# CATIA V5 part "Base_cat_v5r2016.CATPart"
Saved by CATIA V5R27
Part number: Base
Nomenclature: 1
Bounding box of the stored display mesh (mm): x -32 to 32, y 0 to 144, z 0 to 52
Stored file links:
  E:\_Deepak\2017_Deepak\CATIA\Resources\Tutorial Files\Tutorials\c13_catia_v5_6r2016_tut\c13tut2\c13tut02.CATParts\Base_cat_v5r2016.CATPart
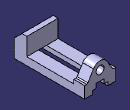
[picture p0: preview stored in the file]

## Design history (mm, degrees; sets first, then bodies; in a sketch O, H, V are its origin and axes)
Body1 (main body)
  Sketch1 on xy-plane, origin (0, 0, 0), H (1, 0, 0), V (0, 1, 0)
    point P1 (-32, 0)
    line L1 (-32, 0) -> (32, 0)
    line L2 (32, 0) -> (32, 144)
    line L3 (32, 144) -> (-32, 144)
    line L4 (-32, 144) -> (-32, 0)
    length L1 = 64
    length L2 = 144
    distance V L2 = 32
    coincidence: P1 H
    horizontal: L1 H, L3 H
    vertical: L2 V, L4 V
  Pad1: profile Sketch1, direction (0, 0, 1), length 16
  Sketch2 on face of Pad1, origin (32, 0, 0), H (0, 1, 0), V (0, 0, 1)
    point P1 (0, 16)
    line L1 (0, 16) -> (0, 36)
    point P2 (0, 36)
    line L2 (26, 52) -> (26, 16)
    line L3 (26, 16) -> (0, 16)
    reference projected line E1 (144, 16) -> (0, 16) from edge of Pad1
    line L4 (26, 52) -> (16, 52)
    point P5 (16, 52)
    line L5 (16, 52) -> (0, 36)
    length L2 = 36
    distance P5 P2 H = 16
    distance P5 P2 V = 16
    length L3 = 26
    coincidence: P1 V, E1 L3
    vertical: L1 V, L2 V
    horizontal: L3 H, L4 H
  Pad2: profile Sketch2, direction (-1, 0, 0), length 64
  Sketch3 on face of Pad1, origin (0, 144, 0), H (-1, 0, 0), V (0, 0, 1)
    line L1 (-32, 16) -> (-32, 24)
    point P2 (32, 24)
    line L2 (32, 24) -> (32, 16)
    line L3 (32, 16) -> (-32, 16)
    reference projected line E1 (32, 16) -> (-32, 16) from edge of Pad1
    line L4 (32, 24) -> (26, 24)
    point P4 (26, 24)
    line L5 (26, 24) -> (13.6777, 44.3018)
    point P5 (0, 52)
    line L6 (-13.6777, 44.3018) -> (-26, 24)
    point P6 (-26, 24)
    line L7 (-26, 24) -> (-32, 24)
    reference projected line E2 (32, 52) -> (-32, 52) from edge of Pad2
    reference projected line E3 (32, 16) -> (32, 52) from edge of Pad2
    reference projected line E4 (-32, 0) -> (-32, 16) from edge of Pad1
    arc A1 centre (0, 36) radius 16 from (13.6777, 44.3018) to (-13.6777, 44.3018) ccw
    point P8 (0, 36)
    reference projected line E5 (32, 52) -> (-32, 52) from edge of Pad2
    circle A2 centre (0, 36) radius 8
    distance H P2 = 24
    distance P6 P4 = 52
    distance P6 V = 26
    radius A1 = 16
    radius A2 = 8
    vertical: L1 V, L2 V
    horizontal: L3 H, L4 H, L7 H
    coincidence: L3 E1, P5 V, P6 L4, P5 E2, L2 E3, L1 E4, P8 V
    tangency: A1 E5, L6 A1, A1 L5
  Pad3: profile Sketch3, direction (0, -1, 0), length 22
  Fillet1: radius 3, on 2 edges
  Sketch4 on face of Pad1, origin (0, 144, 0), H (-1, 0, 0), V (0, 0, 1)
    point P1 (-16, 0)
    line L1 (-16, 0) -> (-16, 7)
    point P2 (-16, 7)
    line L2 (-16, 7) -> (-8, 7)
    point P3 (-8, 7)
    line L3 (-8, 7) -> (-8, 16)
    point P4 (-8, 16)
    line L4 (-8, 16) -> (0, 16)
    point P5 (0, 16)
    point P6 (16, 7)
    point P7 (16, 0)
    line L5 (16, 0) -> (16, 7)
    point P8 (8, 7)
    line L6 (16, 7) -> (8, 7)
    point P9 (8, 16)
    line L7 (8, 7) -> (8, 16)
    point P10 (0, 16)
    line L8 (8, 16) -> (0, 16)
    line L9 (-16, 0) -> (16, 0)
    point P11 (16, 0)
    distance L1 V = 16
    distance L3 V = 8
    distance H L4 = 16
    distance H L2 = 7
    coincidence: P1 H, P5 V, P7 P11, P5 P10
    vertical: L1 V, L3 V
    horizontal: L2 H, L4 H, L9 H
    symmetry: P2 P6 V, P1 P7 V, L1 L5 V, P3 P8 V, L2 L6 V, P4 P9 V, L3 L7 V, P5 P10 V, L4 L8 V
  Pocket1: profile Sketch4, direction (0, -1, 0), through (limit type 3)
  Sketch5 on face of Pad1, origin (0, 0, 0), H (1, 0, 0), V (0, -1, 0)
    circle A1 centre (22, -38) radius 3
    point P1 (22, -38)
    reference projected line E1 (32, 0) -> (-32, 0) from edge of Pad1
    radius A1 = 3
    distance P1 E1 = 38
    distance V P1 = 22
  Pocket2: profile Sketch5, direction (0, 0, 1), length 12
  RectPattern1: of Pocket2, direction 1 instances 2, spacing 70, along edge of Pad1, direction 2 instances 2, spacing 44, along edge of Pad1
